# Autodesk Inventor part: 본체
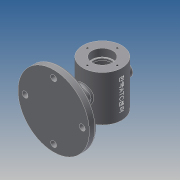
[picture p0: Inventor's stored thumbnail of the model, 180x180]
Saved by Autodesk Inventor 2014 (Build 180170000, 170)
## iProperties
Created: 2018-12
Part Number: 본체
Material: Generic
Document SubType Name: Modeling
Designer: kb542-13
Density: 1 g/cm^3
Appearance: Default
Author: kb542-13
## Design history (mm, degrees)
sketch "스케치1"
  geometry: C1 r 30 at (0, 0); 1 further point
  constraints: 1 centre point, 1 coincident
  dimensions: "d0" = 60 diameter of C1
extrude "돌출1" new body sketch "스케치1" stored distance "d1" = 70; taper "d2" = 0 deg
sketch "스케치2"
  geometry: L1 (30, 35)-(-30, 35) reference; L2 (0, 35)-(0, -35); L3 (-30, -35)-(30, -35) reference; L4 (16, 35)-(16, 23); L5 (16, 23)-(14, 23); L6 (14, 23)-(14, 20); L7 (14, 20)-(25, 20); L8 (25, 20)-(25, -20); L9 (25, -20)-(14, -20); L10 (14, -20)-(14, -23); L11 (14, -23)-(16, -23); L12 (16, -23)-(16, -35); L13 (16, 35)-(0, 35); L14 (16, -35)-(0, -35); 1 further point
  constraints: 24 end point, 6 parallel, 3 perpendicular, 2 collinear, 2 midpoint, 2 point on line
  dimensions: "d3" = 32 diameter of L4 L2; "d4" = 3 distance of L5.end L6.end; "d5" = 3 distance of L9.end L10.end; "d6" = 50 diameter of L8 L2; "d7" = 40 distance of L7.end L8.end; "d8" = 12 distance of L4.start L4.end; "d9" = 32 diameter of L12 L2; "d10" = 28 diameter of L10 L2; "d11" = 28 diameter of L6 L2
revolve "회전1" sketch "스케치2" stored, may be unused: angle "d12" = 90 deg
node "작업 평면1"
sketch "스케치5"
  geometry: L1 (-30, -35)-(-30, 35) reference; L2 (-30, 0)-(-75, 0); L3 (-75, 0)-(-75, 55); L4 (-75, 55)-(-64, 55); L5 (-64, 55)-(-49.263, 0); 1 further point
  constraints: 8 end point, 2 perpendicular, 1 midpoint, 1 parallel, 1 point on line
  dimensions: "d27" = 75 distance from line of point (0, 0) L3; "d28" = 11 distance of L3.end L4.end; "d29" = 75 deg angle of L5 L4; "d30" = 110 diameter of L4 L2
revolve "회전3" sketch "스케치5" stored, may be unused: angle "d31" = 90 deg
node "작업 평면2"
sketch "스케치6"
  geometry: C1 r 12 at (0, 0); 1 further point
  constraints: 1 centre point, 1 coincident
  dimensions: "d33" = 24 diameter of C1
extrude "돌출2" join sketch "스케치6" stored distance "d34" = 11; taper "d35" = 0 deg
node "작업 평면3"
sketch "스케치8"
  geometry: C1 r 4.5 at (0, 44); 1 further point
  constraints: 1 centre point, 1 vertical alignment
  dimensions: "d37" = 44 distance of point (0, 0) C1.centre; "d38" = 9 diameter of C1
extrude "돌출3" cut sketch "스케치8" distance "d39" = 11; taper "d40" = 0 deg
sketch "스케치9"
  geometry: C1 r 4.5 at (0, 44) reference; C2 r 7 at (0, 44); 1 further point
  constraints: 1 centre point, 1 coincident
  dimensions: "d44" = 14 diameter of C2
extrude "돌출4" cut sketch "스케치9" stored distance "d45" = 11; taper "d46" = 0 deg
sketch "스케치10"
  geometry: C1 r 16 at (0, 0) reference; 1 further point
  constraints: 1 vertical alignment
  dimensions: "d50" = 23 distance of C1.centre point (0, 23)
hole "구멍1" sketch "스케치10" at (0, 23) diameter "d51" = 3.242; stored, may be unused: countersink angle "d55" = 90 deg, drill point angle "d57" = 118 deg; dims "d52" = 8, "d53" = 4, "d54" = 2, "d56" = 10
node "작업 평면4"
sketch "스케치11"
  geometry: C1 r 10 at (0, 0); 1 further point
  constraints: 1 centre point, 1 coincident
  dimensions: "d62" = 20 diameter of C1
extrude "돌출5" join sketch "스케치11" stored distance "d63" = 11; taper "d64" = 0 deg
sketch "스케치12"
  geometry: C1 r 10 at (0, 0) reference; C2 r 5 at (0, 0)
  constraints: 1 centre point, 1 coincident
  dimensions: "d65" = 10 diameter of C2
extrude "돌출6" cut sketch "스케치12" stored distance "d66" = 11; taper "d67" = 0 deg
fillet "모깎기1" dims "d68" = 0.3
fillet "모깎기2" dims "d69" = 0.3
fillet "모깎기3" dims "d70" = 3
node "작업 평면5"
sketch "스케치14"
  geometry: L1 (30, 35)-(-30, 35) reference; L2 (30, -35)-(30, 35) reference; 2 further points
  constraints: 1 other
  dimensions: "d72" = 30 distance from line of L2 point (0, 0); "d73" = 35 distance from line of point (0, 0) L1
feature "엠보싱1" sketch "스케치14" dims "d13" = -75, "d74" = 0.5, "d75" = 0
node "솔리드1"
pattern_circular "원형 패턴1" dims angle "d42" = 360 deg
pattern_circular "원형 패턴2" dims angle "d48" = 360 deg
pattern_circular "원형 패턴3" dims angle "d59" = 360 deg
mirror "대칭1"
other parameters: "d61" = -112, "d71" = 58.75
